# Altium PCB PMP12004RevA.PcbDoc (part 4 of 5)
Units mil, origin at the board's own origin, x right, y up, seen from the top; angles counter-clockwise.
Board outline 5500 x 4500 mil, 6 copper layers (Top Layer, GND, Signal Layer 1, Signal Layer 2, PWR Split, Bottom Layer), stack 0 mil thick; 355 components, 130 nets, 833 pads, 904 vias.
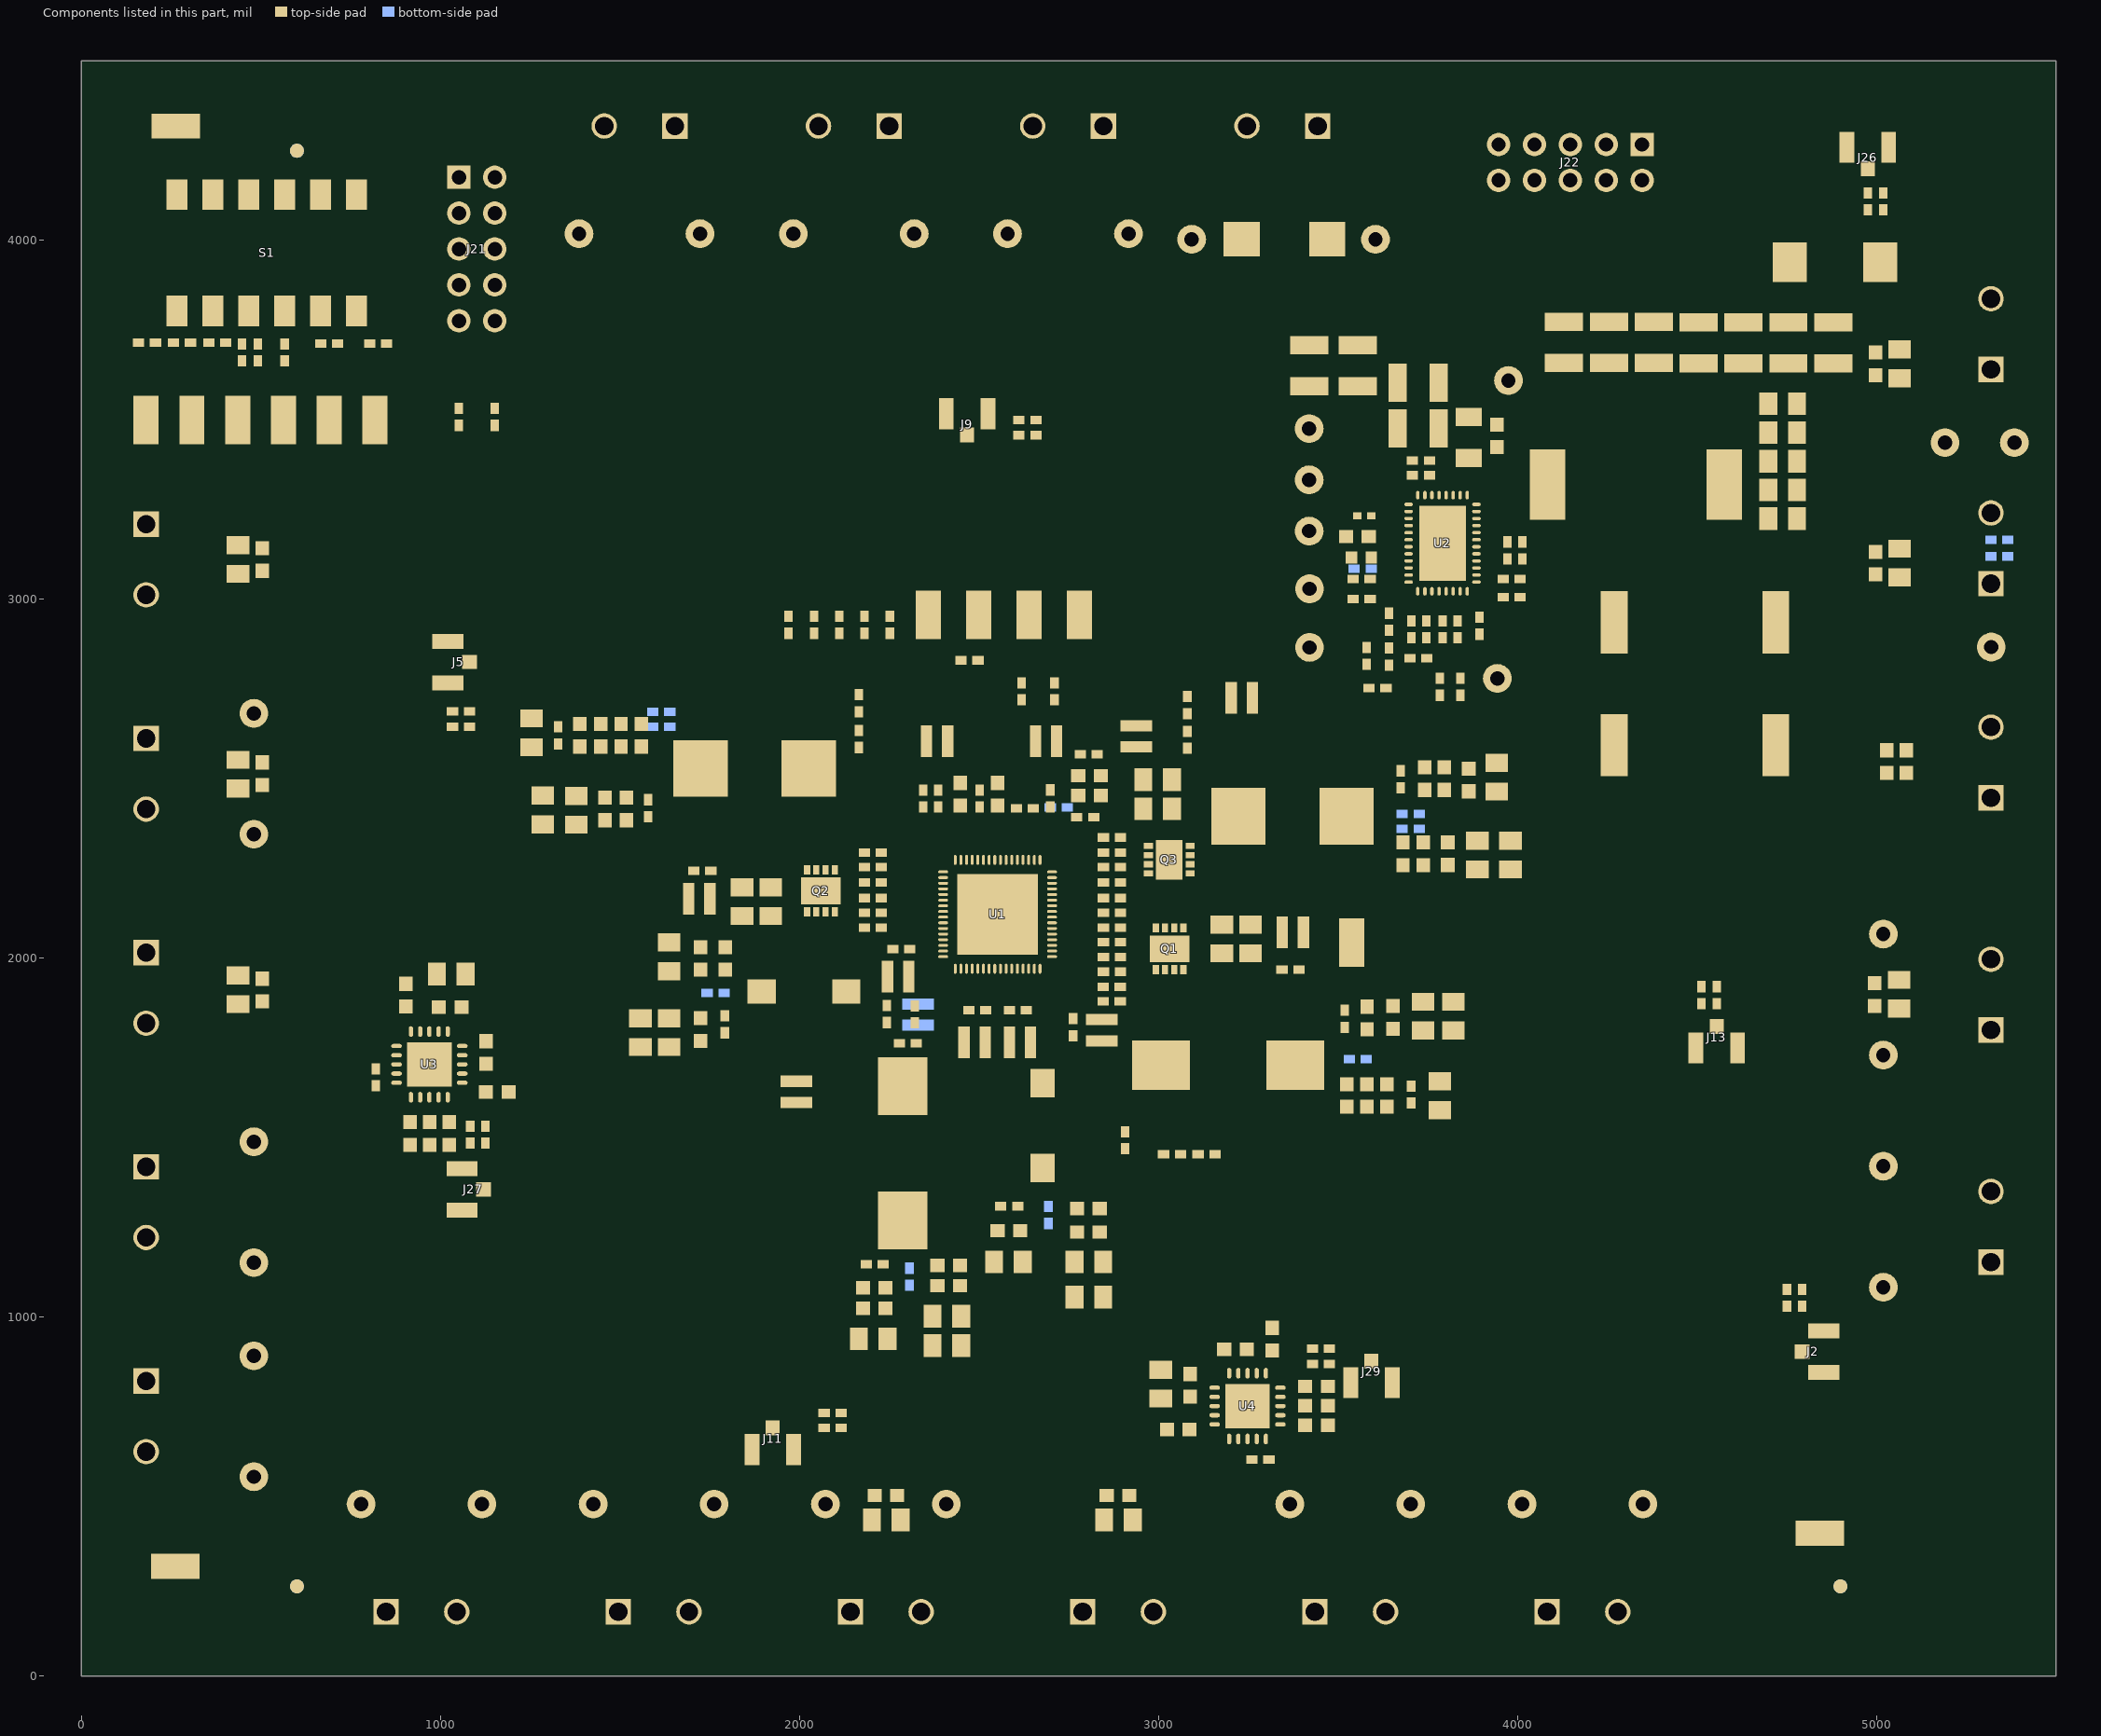
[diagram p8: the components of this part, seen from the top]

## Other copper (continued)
GND:
  pour cut-out: 1335.59,4019 1337.31,4032.05 1342.35,4044.22 1350.36,4054.66 1360.81,4062.67 1372.97,4067.71 1386.02,4069.43 1399.08,4067.71 1411.24,4062.67 1421.69,4054.66 1429.7,4044.22 1434.74,4032.05 1436.46,4019 1434.74,4005.95 1429.7,3993.78 1421.69,3983.34 1411.24,3975.33 1399.08,3970.29 1386.02,3968.57 1372.97,3970.29 1360.81,3975.33 1350.36,3983.34 1342.35,3993.78 1337.31,4005.95
  pour cut-out: 1672.44,4019 1674.16,4032.05 1679.2,4044.22 1687.21,4054.66 1697.66,4062.67 1709.82,4067.71 1722.87,4069.43 1735.93,4067.71 1748.09,4062.67 1758.54,4054.66 1766.55,4044.22 1771.59,4032.05 1773.31,4019 1771.59,4005.95 1766.55,3993.78 1758.54,3983.34 1748.09,3975.33 1735.93,3970.29 1722.87,3968.57 1709.82,3970.29 1697.66,3975.33 1687.21,3983.34 1679.2,3993.78 1674.16,4005.95
  pour cut-out: 1932.44,4019 1934.16,4032.05 1939.2,4044.22 1947.21,4054.66 1957.66,4062.67 1969.82,4067.71 1982.87,4069.43 1995.93,4067.71 2008.09,4062.67 2018.54,4054.66 2026.55,4044.22 2031.59,4032.05 2033.31,4019 2031.59,4005.95 2026.55,3993.78 2018.54,3983.34 2008.09,3975.33 1995.93,3970.29 1982.87,3968.57 1969.82,3970.29 1957.66,3975.33 1947.21,3983.34 1939.2,3993.78 1934.16,4005.95
  pour cut-out: 2269.29,4019 2271.01,4032.05 2276.05,4044.22 2284.06,4054.66 2294.51,4062.67 2306.67,4067.71 2319.72,4069.43 2332.78,4067.71 2344.94,4062.67 2355.39,4054.66 2363.4,4044.22 2368.44,4032.05 2370.16,4019 2368.44,4005.95 2363.4,3993.78 2355.39,3983.34 2344.94,3975.33 2332.78,3970.29 2319.72,3968.57 2306.67,3970.29 2294.51,3975.33 2284.06,3983.34 2276.05,3993.78 2271.01,4005.95
  pour cut-out: 2529.29,4019 2531.01,4032.05 2536.05,4044.22 2544.06,4054.66 2554.51,4062.67 2566.67,4067.71 2579.72,4069.43 2592.78,4067.71 2604.94,4062.67 2615.39,4054.66 2623.4,4044.22 2628.44,4032.05 2630.16,4019 2628.44,4005.95 2623.4,3993.78 2615.39,3983.34 2604.94,3975.33 2592.78,3970.29 2579.72,3968.57 2566.67,3970.29 2554.51,3975.33 2544.06,3983.34 2536.05,3993.78 2531.01,4005.95
  pour cut-out: 2866.14,4019 2867.86,4032.05 2872.9,4044.22 2880.91,4054.66 2891.36,4062.67 2903.52,4067.71 2916.57,4069.43 2929.63,4067.71 2941.79,4062.67 2952.24,4054.66 2960.25,4044.22 2965.29,4032.05 2967.01,4019 2965.29,4005.95 2960.25,3993.78 2952.24,3983.34 2941.79,3975.33 2929.63,3970.29 2916.57,3968.57 2903.52,3970.29 2891.36,3975.33 2880.91,3983.34 2872.9,3993.78 2867.86,4005.95
  pour cut-out: 4968.9,2067.19 4970.62,2080.25 4975.66,2092.41 4983.67,2102.85 4994.12,2110.87 5006.28,2115.91 5019.33,2117.63 5032.38,2115.91 5044.55,2110.87 5054.99,2102.85 5063.01,2092.41 5068.05,2080.25 5069.76,2067.19 5068.05,2054.14 5063.01,2041.98 5054.99,2031.53 5044.55,2023.52 5032.38,2018.48 5019.33,2016.76 5006.28,2018.48 4994.12,2023.52 4983.67,2031.53 4975.66,2041.98 4970.62,2054.14
  pour cut-out: 4968.9,1730.34 4970.62,1743.4 4975.66,1755.56 4983.67,1766 4994.12,1774.02 5006.28,1779.06 5019.33,1780.78 5032.38,1779.06 5044.55,1774.02 5054.99,1766 5063.01,1755.56 5068.05,1743.4 5069.76,1730.34 5068.05,1717.29 5063.01,1705.13 5054.99,1694.68 5044.55,1686.67 5032.38,1681.63 5019.33,1679.91 5006.28,1681.63 4994.12,1686.67 4983.67,1694.68 4975.66,1705.13 4970.62,1717.29
  pour cut-out: 4968.9,1420.34 4970.62,1433.4 4975.66,1445.56 4983.67,1456 4994.12,1464.02 5006.28,1469.06 5019.33,1470.78 5032.38,1469.06 5044.55,1464.02 5054.99,1456 5063.01,1445.56 5068.05,1433.4 5069.76,1420.34 5068.05,1407.29 5063.01,1395.13 5054.99,1384.68 5044.55,1376.67 5032.38,1371.63 5019.33,1369.91 5006.28,1371.63 4994.12,1376.67 4983.67,1384.68 4975.66,1395.13 4970.62,1407.29
  pour cut-out: 4968.9,1083.49 4970.62,1096.55 4975.66,1108.71 4983.67,1119.15 4994.12,1127.17 5006.28,1132.21 5019.33,1133.93 5032.38,1132.21 5044.55,1127.17 5054.99,1119.15 5063.01,1108.71 5068.05,1096.55 5069.76,1083.49 5068.05,1070.44 5063.01,1058.28 5054.99,1047.83 5044.55,1039.82 5032.38,1034.78 5019.33,1033.06 5006.28,1034.78 4994.12,1039.82 4983.67,1047.83 4975.66,1058.28 4970.62,1070.44
  pour cut-out: 4299.24,479 4300.96,492.05 4306,504.22 4314.01,514.66 4324.46,522.67 4336.62,527.71 4349.68,529.43 4362.73,527.71 4374.89,522.67 4385.34,514.66 4393.35,504.22 4398.39,492.05 4400.11,479 4398.39,465.95 4393.35,453.78 4385.34,443.34 4374.89,435.33 4362.73,430.29 4349.68,428.57 4336.62,430.29 4324.46,435.33 4314.01,443.34 4306,453.78 4300.96,465.95
  pour cut-out: 3962.39,479 3964.11,492.05 3969.15,504.22 3977.16,514.66 3987.61,522.67 3999.77,527.71 4012.83,529.43 4025.88,527.71 4038.04,522.67 4048.49,514.66 4056.5,504.22 4061.54,492.05 4063.26,479 4061.54,465.95 4056.5,453.78 4048.49,443.34 4038.04,435.33 4025.88,430.29 4012.83,428.57 3999.77,430.29 3987.61,435.33 3977.16,443.34 3969.15,453.78 3964.11,465.95
  pour cut-out: 3652.39,479 3654.11,492.05 3659.15,504.22 3667.16,514.66 3677.61,522.67 3689.77,527.71 3702.83,529.43 3715.88,527.71 3728.04,522.67 3738.49,514.66 3746.5,504.22 3751.54,492.05 3753.26,479 3751.54,465.95 3746.5,453.78 3738.49,443.34 3728.04,435.33 3715.88,430.29 3702.83,428.57 3689.77,430.29 3677.61,435.33 3667.16,443.34 3659.15,453.78 3654.11,465.95
  pour cut-out: 3315.54,479 3317.26,492.05 3322.3,504.22 3330.31,514.66 3340.76,522.67 3352.92,527.71 3365.98,529.43 3379.03,527.71 3391.19,522.67 3401.64,514.66 3409.65,504.22 3414.69,492.05 3416.41,479 3414.69,465.95 3409.65,453.78 3401.64,443.34 3391.19,435.33 3379.03,430.29 3365.98,428.57 3352.92,430.29 3340.76,435.33 3330.31,443.34 3322.3,453.78 3317.26,465.95
  pour cut-out: 2358.69,479 2360.41,492.05 2365.45,504.22 2373.46,514.66 2383.91,522.67 2396.07,527.71 2409.13,529.43 2422.18,527.71 2434.34,522.67 2444.79,514.66 2452.8,504.22 2457.84,492.05 2459.56,479 2457.84,465.95 2452.8,453.78 2444.79,443.34 2434.34,435.33 2422.18,430.29 2409.13,428.57 2396.07,430.29 2383.91,435.33 2373.46,443.34 2365.45,453.78 2360.41,465.95
  pour cut-out: 2021.84,479 2023.56,492.05 2028.6,504.22 2036.61,514.66 2047.06,522.67 2059.22,527.71 2072.28,529.43 2085.33,527.71 2097.49,522.67 2107.94,514.66 2115.95,504.22 2120.99,492.05 2122.71,479 2120.99,465.95 2115.95,453.78 2107.94,443.34 2097.49,435.33 2085.33,430.29 2072.28,428.57 2059.22,430.29 2047.06,435.33 2036.61,443.34 2028.6,453.78 2023.56,465.95
  pour cut-out: 1711.84,479 1713.56,492.05 1718.6,504.22 1726.61,514.66 1737.06,522.67 1749.22,527.71 1762.28,529.43 1775.33,527.71 1787.49,522.67 1797.94,514.66 1805.95,504.22 1810.99,492.05 1812.71,479 1810.99,465.95 1805.95,453.78 1797.94,443.34 1787.49,435.33 1775.33,430.29 1762.28,428.57 1749.22,430.29 1737.06,435.33 1726.61,443.34 1718.6,453.78 1713.56,465.95
  pour cut-out: 1374.99,479 1376.71,492.05 1381.75,504.22 1389.76,514.66 1400.21,522.67 1412.37,527.71 1425.43,529.43 1438.48,527.71 1450.64,522.67 1461.09,514.66 1469.1,504.22 1474.14,492.05 1475.86,479 1474.14,465.95 1469.1,453.78 1461.09,443.34 1450.64,435.33 1438.48,430.29 1425.43,428.57 1412.37,430.29 1400.21,435.33 1389.76,443.34 1381.75,453.78 1376.71,465.95
  pour cut-out: 1064.99,479 1066.71,492.05 1071.75,504.22 1079.76,514.66 1090.21,522.67 1102.37,527.71 1115.43,529.43 1128.48,527.71 1140.64,522.67 1151.09,514.66 1159.1,504.22 1164.14,492.05 1165.86,479 1164.14,465.95 1159.1,453.78 1151.09,443.34 1140.64,435.33 1128.48,430.29 1115.43,428.57 1102.37,430.29 1090.21,435.33 1079.76,443.34 1071.75,453.78 1066.71,465.95
  pour cut-out: 728.14,479 729.86,492.05 734.9,504.22 742.91,514.66 753.36,522.67 765.52,527.71 778.58,529.43 791.63,527.71 803.79,522.67 814.24,514.66 822.25,504.22 827.29,492.05 829.01,479 827.29,465.95 822.25,453.78 814.24,443.34 803.79,435.33 791.63,430.29 778.58,428.57 765.52,430.29 753.36,435.33 742.91,443.34 734.9,453.78 729.86,465.95
  pour cut-out: 429.57,555.17 431.29,568.23 436.33,580.39 444.34,590.84 454.78,598.85 466.95,603.89 480,605.61 493.05,603.89 505.22,598.85 515.66,590.84 523.67,580.39 528.71,568.23 530.43,555.17 528.71,542.12 523.67,529.96 515.66,519.51 505.22,511.5 493.05,506.46 480,504.74 466.95,506.46 454.78,511.5 444.34,519.51 436.33,529.96 431.29,542.12
  pour cut-out: 429.57,892.02 431.29,905.08 436.33,917.24 444.34,927.69 454.78,935.7 466.95,940.74 480,942.46 493.05,940.74 505.22,935.7 515.66,927.69 523.67,917.24 528.71,905.08 530.43,892.02 528.71,878.97 523.67,866.81 515.66,856.36 505.22,848.35 493.05,843.31 480,841.59 466.95,843.31 454.78,848.35 444.34,856.36 436.33,866.81 431.29,878.97
  pour cut-out: 429.57,1488.87 431.29,1501.93 436.33,1514.09 444.34,1524.54 454.78,1532.55 466.95,1537.59 480,1539.31 493.05,1537.59 505.22,1532.55 515.66,1524.54 523.67,1514.09 528.71,1501.93 530.43,1488.87 528.71,1475.82 523.67,1463.66 515.66,1453.21 505.22,1445.2 493.05,1440.16 480,1438.44 466.95,1440.16 454.78,1445.2 444.34,1453.21 436.33,1463.66 431.29,1475.82
  pour cut-out: 429.57,2345.72 431.29,2358.78 436.33,2370.94 444.34,2381.39 454.78,2389.4 466.95,2394.44 480,2396.16 493.05,2394.44 505.22,2389.4 515.66,2381.39 523.67,2370.94 528.71,2358.78 530.43,2345.72 528.71,2332.67 523.67,2320.51 515.66,2310.06 505.22,2302.05 493.05,2297.01 480,2295.29 466.95,2297.01 454.78,2302.05 444.34,2310.06 436.33,2320.51 431.29,2332.67
  pour cut-out: 429.57,2682.57 431.29,2695.63 436.33,2707.79 444.34,2718.24 454.78,2726.25 466.95,2731.29 480,2733.01 493.05,2731.29 505.22,2726.25 515.66,2718.24 523.67,2707.79 528.71,2695.63 530.43,2682.57 528.71,2669.52 523.67,2657.36 515.66,2646.91 505.22,2638.9 493.05,2633.86 480,2632.14 466.95,2633.86 454.78,2638.9 444.34,2646.91 436.33,2657.36 431.29,2669.52
  pour cut-out: 429.57,1152.02 431.29,1165.08 436.33,1177.24 444.34,1187.69 454.78,1195.7 466.95,1200.74 480,1202.46 493.05,1200.74 505.22,1195.7 515.66,1187.69 523.67,1177.24 528.71,1165.08 530.43,1152.02 528.71,1138.97 523.67,1126.81 515.66,1116.36 505.22,1108.35 493.05,1103.31 480,1101.59 466.95,1103.31 454.78,1108.35 444.34,1116.36 436.33,1126.81 431.29,1138.97
  pour cut-out: 5269.66,2867.18 5271.38,2880.23 5276.42,2892.39 5284.43,2902.84 5294.87,2910.85 5307.04,2915.89 5320.09,2917.61 5333.14,2915.89 5345.31,2910.85 5355.75,2902.84 5363.76,2892.39 5368.8,2880.23 5370.52,2867.18 5368.8,2854.12 5363.76,2841.96 5355.75,2831.52 5345.31,2823.5 5333.14,2818.46 5320.09,2816.74 5307.04,2818.46 5294.87,2823.5 5284.43,2831.52 5276.42,2841.96 5271.38,2854.12
  pour cut-out: 2310.49,2160.97 cw(c2310.49,2175.97) 2295.49,2175.97 cw(c2310.49,2175.97) 2310.49,2190.97 cw(c2310.49,2175.97) 2325.49,2175.97 cw(c2310.49,2175.97)
  pour cut-out: 2780.69,2112.34 cw(c2780.69,2127.34) 2765.69,2127.34 cw(c2780.69,2127.34) 2780.69,2142.34 cw(c2780.69,2127.34) 2795.69,2127.34 cw(c2780.69,2127.34)
  pour cut-out: 2785.08,2036.6 cw(c2785.08,2051.6) 2770.08,2051.6 cw(c2785.08,2051.6) 2785.08,2066.6 cw(c2785.08,2051.6) 2800.08,2051.6 cw(c2785.08,2051.6)
  pour cut-out: 3037.13,2179.63 cw(c3037.13,2194.63) 3022.13,2194.63 cw(c3037.13,2194.63) 3037.13,2209.63 cw(c3037.13,2194.63) 3052.13,2194.63 cw(c3037.13,2194.63)
  pour cut-out: 2952.65,2003.85 cw(c2952.65,2018.85) 2937.65,2018.85 cw(c2952.65,2018.85) 2952.65,2033.85 cw(c2952.65,2018.85) 2967.65,2018.85 cw(c2952.65,2018.85)
  pour cut-out: 2138.36,2180.07 cw(c2138.36,2195.07) 2123.36,2195.07 cw(c2138.36,2195.07) 2138.36,2210.07 cw(c2138.36,2195.07) 2153.36,2195.07 cw(c2138.36,2195.07)
  text "2" at 4712.44,637.86 h100
  text ".Layer_Name" at 577,-858.49 h60
Signal Layer 1:
  pour cut-out: 1335.59,4019 1337.31,4032.05 1342.35,4044.22 1350.36,4054.66 1360.81,4062.67 1372.97,4067.71 1386.02,4069.43 1399.08,4067.71 1411.24,4062.67 1421.69,4054.66 1429.7,4044.22 1434.74,4032.05 1436.46,4019 1434.74,4005.95 1429.7,3993.78 1421.69,3983.34 1411.24,3975.33 1399.08,3970.29 1386.02,3968.57 1372.97,3970.29 1360.81,3975.33 1350.36,3983.34 1342.35,3993.78 1337.31,4005.95
  pour cut-out: 1672.44,4019 1674.16,4032.05 1679.2,4044.22 1687.21,4054.66 1697.66,4062.67 1709.82,4067.71 1722.87,4069.43 1735.93,4067.71 1748.09,4062.67 1758.54,4054.66 1766.55,4044.22 1771.59,4032.05 1773.31,4019 1771.59,4005.95 1766.55,3993.78 1758.54,3983.34 1748.09,3975.33 1735.93,3970.29 1722.87,3968.57 1709.82,3970.29 1697.66,3975.33 1687.21,3983.34 1679.2,3993.78 1674.16,4005.95
  pour cut-out: 1932.44,4019 1934.16,4032.05 1939.2,4044.22 1947.21,4054.66 1957.66,4062.67 1969.82,4067.71 1982.87,4069.43 1995.93,4067.71 2008.09,4062.67 2018.54,4054.66 2026.55,4044.22 2031.59,4032.05 2033.31,4019 2031.59,4005.95 2026.55,3993.78 2018.54,3983.34 2008.09,3975.33 1995.93,3970.29 1982.87,3968.57 1969.82,3970.29 1957.66,3975.33 1947.21,3983.34 1939.2,3993.78 1934.16,4005.95
  pour cut-out: 2269.29,4019 2271.01,4032.05 2276.05,4044.22 2284.06,4054.66 2294.51,4062.67 2306.67,4067.71 2319.72,4069.43 2332.78,4067.71 2344.94,4062.67 2355.39,4054.66 2363.4,4044.22 2368.44,4032.05 2370.16,4019 2368.44,4005.95 2363.4,3993.78 2355.39,3983.34 2344.94,3975.33 2332.78,3970.29 2319.72,3968.57 2306.67,3970.29 2294.51,3975.33 2284.06,3983.34 2276.05,3993.78 2271.01,4005.95
  pour cut-out: 2529.29,4019 2531.01,4032.05 2536.05,4044.22 2544.06,4054.66 2554.51,4062.67 2566.67,4067.71 2579.72,4069.43 2592.78,4067.71 2604.94,4062.67 2615.39,4054.66 2623.4,4044.22 2628.44,4032.05 2630.16,4019 2628.44,4005.95 2623.4,3993.78 2615.39,3983.34 2604.94,3975.33 2592.78,3970.29 2579.72,3968.57 2566.67,3970.29 2554.51,3975.33 2544.06,3983.34 2536.05,3993.78 2531.01,4005.95
  pour cut-out: 2866.14,4019 2867.86,4032.05 2872.9,4044.22 2880.91,4054.66 2891.36,4062.67 2903.52,4067.71 2916.57,4069.43 2929.63,4067.71 2941.79,4062.67 2952.24,4054.66 2960.25,4044.22 2965.29,4032.05 2967.01,4019 2965.29,4005.95 2960.25,3993.78 2952.24,3983.34 2941.79,3975.33 2929.63,3970.29 2916.57,3968.57 2903.52,3970.29 2891.36,3975.33 2880.91,3983.34 2872.9,3993.78 2867.86,4005.95
  pour cut-out: 4968.9,2067.19 4970.62,2080.25 4975.66,2092.41 4983.67,2102.85 4994.12,2110.87 5006.28,2115.91 5019.33,2117.63 5032.38,2115.91 5044.55,2110.87 5054.99,2102.85 5063.01,2092.41 5068.05,2080.25 5069.76,2067.19 5068.05,2054.14 5063.01,2041.98 5054.99,2031.53 5044.55,2023.52 5032.38,2018.48 5019.33,2016.76 5006.28,2018.48 4994.12,2023.52 4983.67,2031.53 4975.66,2041.98 4970.62,2054.14
  pour cut-out: 4968.9,1730.34 4970.62,1743.4 4975.66,1755.56 4983.67,1766 4994.12,1774.02 5006.28,1779.06 5019.33,1780.78 5032.38,1779.06 5044.55,1774.02 5054.99,1766 5063.01,1755.56 5068.05,1743.4 5069.76,1730.34 5068.05,1717.29 5063.01,1705.13 5054.99,1694.68 5044.55,1686.67 5032.38,1681.63 5019.33,1679.91 5006.28,1681.63 4994.12,1686.67 4983.67,1694.68 4975.66,1705.13 4970.62,1717.29
  pour cut-out: 4968.9,1420.34 4970.62,1433.4 4975.66,1445.56 4983.67,1456 4994.12,1464.02 5006.28,1469.06 5019.33,1470.78 5032.38,1469.06 5044.55,1464.02 5054.99,1456 5063.01,1445.56 5068.05,1433.4 5069.76,1420.34 5068.05,1407.29 5063.01,1395.13 5054.99,1384.68 5044.55,1376.67 5032.38,1371.63 5019.33,1369.91 5006.28,1371.63 4994.12,1376.67 4983.67,1384.68 4975.66,1395.13 4970.62,1407.29
  pour cut-out: 4968.9,1083.49 4970.62,1096.55 4975.66,1108.71 4983.67,1119.15 4994.12,1127.17 5006.28,1132.21 5019.33,1133.93 5032.38,1132.21 5044.55,1127.17 5054.99,1119.15 5063.01,1108.71 5068.05,1096.55 5069.76,1083.49 5068.05,1070.44 5063.01,1058.28 5054.99,1047.83 5044.55,1039.82 5032.38,1034.78 5019.33,1033.06 5006.28,1034.78 4994.12,1039.82 4983.67,1047.83 4975.66,1058.28 4970.62,1070.44
  pour cut-out: 4299.24,479 4300.96,492.05 4306,504.22 4314.01,514.66 4324.46,522.67 4336.62,527.71 4349.68,529.43 4362.73,527.71 4374.89,522.67 4385.34,514.66 4393.35,504.22 4398.39,492.05 4400.11,479 4398.39,465.95 4393.35,453.78 4385.34,443.34 4374.89,435.33 4362.73,430.29 4349.68,428.57 4336.62,430.29 4324.46,435.33 4314.01,443.34 4306,453.78 4300.96,465.95
  pour cut-out: 3962.39,479 3964.11,492.05 3969.15,504.22 3977.16,514.66 3987.61,522.67 3999.77,527.71 4012.83,529.43 4025.88,527.71 4038.04,522.67 4048.49,514.66 4056.5,504.22 4061.54,492.05 4063.26,479 4061.54,465.95 4056.5,453.78 4048.49,443.34 4038.04,435.33 4025.88,430.29 4012.83,428.57 3999.77,430.29 3987.61,435.33 3977.16,443.34 3969.15,453.78 3964.11,465.95
  pour cut-out: 3652.39,479 3654.11,492.05 3659.15,504.22 3667.16,514.66 3677.61,522.67 3689.77,527.71 3702.83,529.43 3715.88,527.71 3728.04,522.67 3738.49,514.66 3746.5,504.22 3751.54,492.05 3753.26,479 3751.54,465.95 3746.5,453.78 3738.49,443.34 3728.04,435.33 3715.88,430.29 3702.83,428.57 3689.77,430.29 3677.61,435.33 3667.16,443.34 3659.15,453.78 3654.11,465.95
  pour cut-out: 3315.54,479 3317.26,492.05 3322.3,504.22 3330.31,514.66 3340.76,522.67 3352.92,527.71 3365.98,529.43 3379.03,527.71 3391.19,522.67 3401.64,514.66 3409.65,504.22 3414.69,492.05 3416.41,479 3414.69,465.95 3409.65,453.78 3401.64,443.34 3391.19,435.33 3379.03,430.29 3365.98,428.57 3352.92,430.29 3340.76,435.33 3330.31,443.34 3322.3,453.78 3317.26,465.95
  pour cut-out: 2358.69,479 2360.41,492.05 2365.45,504.22 2373.46,514.66 2383.91,522.67 2396.07,527.71 2409.13,529.43 2422.18,527.71 2434.34,522.67 2444.79,514.66 2452.8,504.22 2457.84,492.05 2459.56,479 2457.84,465.95 2452.8,453.78 2444.79,443.34 2434.34,435.33 2422.18,430.29 2409.13,428.57 2396.07,430.29 2383.91,435.33 2373.46,443.34 2365.45,453.78 2360.41,465.95
  pour cut-out: 2021.84,479 2023.56,492.05 2028.6,504.22 2036.61,514.66 2047.06,522.67 2059.22,527.71 2072.28,529.43 2085.33,527.71 2097.49,522.67 2107.94,514.66 2115.95,504.22 2120.99,492.05 2122.71,479 2120.99,465.95 2115.95,453.78 2107.94,443.34 2097.49,435.33 2085.33,430.29 2072.28,428.57 2059.22,430.29 2047.06,435.33 2036.61,443.34 2028.6,453.78 2023.56,465.95
  pour cut-out: 1711.84,479 1713.56,492.05 1718.6,504.22 1726.61,514.66 1737.06,522.67 1749.22,527.71 1762.28,529.43 1775.33,527.71 1787.49,522.67 1797.94,514.66 1805.95,504.22 1810.99,492.05 1812.71,479 1810.99,465.95 1805.95,453.78 1797.94,443.34 1787.49,435.33 1775.33,430.29 1762.28,428.57 1749.22,430.29 1737.06,435.33 1726.61,443.34 1718.6,453.78 1713.56,465.95
  pour cut-out: 1374.99,479 1376.71,492.05 1381.75,504.22 1389.76,514.66 1400.21,522.67 1412.37,527.71 1425.43,529.43 1438.48,527.71 1450.64,522.67 1461.09,514.66 1469.1,504.22 1474.14,492.05 1475.86,479 1474.14,465.95 1469.1,453.78 1461.09,443.34 1450.64,435.33 1438.48,430.29 1425.43,428.57 1412.37,430.29 1400.21,435.33 1389.76,443.34 1381.75,453.78 1376.71,465.95
  pour cut-out: 1064.99,479 1066.71,492.05 1071.75,504.22 1079.76,514.66 1090.21,522.67 1102.37,527.71 1115.43,529.43 1128.48,527.71 1140.64,522.67 1151.09,514.66 1159.1,504.22 1164.14,492.05 1165.86,479 1164.14,465.95 1159.1,453.78 1151.09,443.34 1140.64,435.33 1128.48,430.29 1115.43,428.57 1102.37,430.29 1090.21,435.33 1079.76,443.34 1071.75,453.78 1066.71,465.95
  pour cut-out: 728.14,479 729.86,492.05 734.9,504.22 742.91,514.66 753.36,522.67 765.52,527.71 778.58,529.43 791.63,527.71 803.79,522.67 814.24,514.66 822.25,504.22 827.29,492.05 829.01,479 827.29,465.95 822.25,453.78 814.24,443.34 803.79,435.33 791.63,430.29 778.58,428.57 765.52,430.29 753.36,435.33 742.91,443.34 734.9,453.78 729.86,465.95
  pour cut-out: 429.57,555.17 431.29,568.23 436.33,580.39 444.34,590.84 454.78,598.85 466.95,603.89 480,605.61 493.05,603.89 505.22,598.85 515.66,590.84 523.67,580.39 528.71,568.23 530.43,555.17 528.71,542.12 523.67,529.96 515.66,519.51 505.22,511.5 493.05,506.46 480,504.74 466.95,506.46 454.78,511.5 444.34,519.51 436.33,529.96 431.29,542.12
  pour cut-out: 429.57,892.02 431.29,905.08 436.33,917.24 444.34,927.69 454.78,935.7 466.95,940.74 480,942.46 493.05,940.74 505.22,935.7 515.66,927.69 523.67,917.24 528.71,905.08 530.43,892.02 528.71,878.97 523.67,866.81 515.66,856.36 505.22,848.35 493.05,843.31 480,841.59 466.95,843.31 454.78,848.35 444.34,856.36 436.33,866.81 431.29,878.97
  pour cut-out: 429.57,1488.87 431.29,1501.93 436.33,1514.09 444.34,1524.54 454.78,1532.55 466.95,1537.59 480,1539.31 493.05,1537.59 505.22,1532.55 515.66,1524.54 523.67,1514.09 528.71,1501.93 530.43,1488.87 528.71,1475.82 523.67,1463.66 515.66,1453.21 505.22,1445.2 493.05,1440.16 480,1438.44 466.95,1440.16 454.78,1445.2 444.34,1453.21 436.33,1463.66 431.29,1475.82
  pour cut-out: 429.57,2345.72 431.29,2358.78 436.33,2370.94 444.34,2381.39 454.78,2389.4 466.95,2394.44 480,2396.16 493.05,2394.44 505.22,2389.4 515.66,2381.39 523.67,2370.94 528.71,2358.78 530.43,2345.72 528.71,2332.67 523.67,2320.51 515.66,2310.06 505.22,2302.05 493.05,2297.01 480,2295.29 466.95,2297.01 454.78,2302.05 444.34,2310.06 436.33,2320.51 431.29,2332.67
  pour cut-out: 429.57,2682.57 431.29,2695.63 436.33,2707.79 444.34,2718.24 454.78,2726.25 466.95,2731.29 480,2733.01 493.05,2731.29 505.22,2726.25 515.66,2718.24 523.67,2707.79 528.71,2695.63 530.43,2682.57 528.71,2669.52 523.67,2657.36 515.66,2646.91 505.22,2638.9 493.05,2633.86 480,2632.14 466.95,2633.86 454.78,2638.9 444.34,2646.91 436.33,2657.36 431.29,2669.52
  pour cut-out: 429.57,1152.02 431.29,1165.08 436.33,1177.24 444.34,1187.69 454.78,1195.7 466.95,1200.74 480,1202.46 493.05,1200.74 505.22,1195.7 515.66,1187.69 523.67,1177.24 528.71,1165.08 530.43,1152.02 528.71,1138.97 523.67,1126.81 515.66,1116.36 505.22,1108.35 493.05,1103.31 480,1101.59 466.95,1103.31 454.78,1108.35 444.34,1116.36 436.33,1126.81 431.29,1138.97
  pour cut-out: 429.51,891.75 429.51,763.74 492.87,700.38 503.48,711 905.29,711 2008.94,1814.65 2161.01,1814.65 2188.63,1842.27 2218.19,1871.84 2237.42,1871.84 2282.86,1917.27 2282.86,2030.16 2206.03,2106.99 2134.55,2106.99 2124.57,2097.02 2124.57,2078.52 2135.95,2067.14 2196.46,2067.14 2247.69,2015.9 2247.69,1938.33 2219.96,1910.59 2200.74,1910.59 2152.69,1862.55 2144.04,1853.9 1992.82,1853.9 893.21,754.29 522.48,754.29 504.65,772.12 504.65,814.12 530.43,839.91 530.43,898.34
  pour cut-out: 778.58,428.57 925.37,428.57 960.81,464.01 960.81,497.6 956.35,502.05 956.35,565.48 2075.81,1684.94 2276.16,1684.94 2338.68,1747.45 2338.68,1856.45 2308.5,1886.63 2251.76,1886.63 2236.96,1871.84 2219.31,1871.84 2188.47,1840.99 2188.47,1760.69 2153.89,1726.11 2057.97,1726.11 915.72,583.86 915.72,512.57 908.44,505.29 838.15,505.29 814,529.43 778.58,529.43
  pour cut-out: 2072.28,428.57 2110.72,428.57 2132.97,450.81 2225.08,450.81 2258.86,484.59 2258.86,1174.57 2233.4,1200.02 2176.04,1200.02 2160.95,1184.93 2160.95,1164.66 2172.08,1153.53 2210.41,1153.53 2216.84,1147.11 2216.84,522.21 2198.04,503.41 2139.62,503.41 2113.6,529.43 2072.28,529.43
  pour cut-out: 2876.36,1463.34 2876.36,1433.8 2889.29,1420.87 2926.56,1420.87 2940.29,1434.61 2940.29,1455.01 2947.33,1462.06 3068.33,1462.06 3362.12,1168.26 3735.78,1168.26 4176.31,727.74 4176.31,517.32 4157.93,498.95 4087.75,498.95 4057.26,529.43 4012.83,529.43 4012.83,428.57 4058.23,428.57 4081.35,451.69 4182.81,451.69 4220.88,489.75 4220.88,743.91 3755.14,1209.64 3378.39,1209.64 3088.85,1499.18 2912.48,1499.18
  pour cut-out: 3486.24,1619.61 3486.24,1504.5 3499.06,1491.68 3519.68,1491.68 3533.43,1505.43 3533.43,1583.49 3551.52,1601.58 4254.78,1601.58 4633.54,1222.82 4984.89,1222.82 5001.13,1206.58 5001.13,1159.99 4968.9,1127.76 4968.9,1083.49 5069.76,1083.49 5069.76,1131.98 5044.63,1157.12 5044.63,1232.63 5009.15,1268.11 4653.92,1268.11 4280.37,1641.66 3508.3,1641.66
  pour cut-out: 3617.65,2372 3617.65,2348.38 3629.77,2336.26 3651.04,2336.26 3661.36,2346.58 4129.18,2346.58 4592.44,1883.32 4981.73,1883.32 4999.9,1865.15 4999.9,1805.66 4968.9,1774.66 4968.9,1730.34 5069.76,1730.34 5069.76,1772.15 5042.53,1799.38 5042.53,1894.89 5006.52,1930.9 4608.31,1930.9 4145.86,2393.35 3639.03,2393.35
  pour cut-out: 429.57,2682.57 429.57,2547.78 468.31,2509.04 839.99,2509.04 948.29,2617.33 1587.68,2617.33 1613.13,2642.78 1613.13,2728.91 1595.73,2746.3 1575.77,2746.3 1561.23,2731.76 1561.23,2669.04 1551.23,2659.04 928.12,2659.04 822.09,2553.01 520.28,2553.01 505.34,2567.95 505.34,2607.51 530.43,2632.61 530.43,2682.57
  pour cut-out: 1581.07,4010.37 1620.47,4049.76 1654.64,4049.77 1674.3,4069.43 1723.18,4069.43 1723.18,3968.56 1690.17,3968.56 1669.08,3989.65 1651.7,3989.65 1630.94,3968.89 1630.94,3870.35 2628.01,2873.28 2628.01,2823.1 2666.78,2784.34 2666.78,2739.52 2650.37,2723.11 2630.02,2723.11 2587.74,2765.39 2587.74,2849.74 1581.07,3856.41
  pour cut-out: 2173.69,4014.18 2208.32,4048.81 2249.04,4048.81 2269.67,4069.43 2320.01,4069.43 2320.01,3968.71 2295.4,3968.71 2271.72,3992.39 2242.97,3992.39 2225.99,3975.41 2225.99,3597.35 2712.29,3111.05 2712.29,2836.05 2741.26,2807.08 2741.26,2774.88 2727.31,2760.93 2695.37,2760.92 2666.71,2789.59 2666.71,3086.31 2173.69,3579.33
  pour cut-out: 2762.07,2573.12 2762.07,4013.62 2793.03,4044.59 2857.21,4044.59 2881.64,4069.02 2917.02,4069.02 2917.02,3968.57 2890.97,3968.57 2865.71,3993.83 2828.06,3993.83 2811.56,3977.33 2811.56,2651.62 2857.06,2606.12 2857.06,2587.84 2836.95,2567.73 2836.95,2555.09 2854.06,2537.97 2854.06,2453.57 2875.42,2432.22 2882.75,2432.22 2893.72,2421.24 2893.72,2404.45 2881.52,2392.25 2865.61,2392.25 2817.05,2440.81 2817.05,2518.14
  pour cut-out: 157.86,3377.68 195.72,3339.81 195.72,3327.57 210.15,3313.15 210.15,3280.33 256.61,3233.88 256.61,2821.59 194.98,2759.96 194.98,2721.04 206.41,2709.61 206.41,2684.15 239.62,2650.94 239.62,2496.41 184.59,2441.37 173.88,2441.37 155.28,2459.98
  pour cut-out: 2553.46,1324.03 2541.88,1335.61 2541.88,1360.45 2554.04,1372.61 2606.75,1372.7 2637.07,1342.38 2637.07,975.98 2922.58,690.47 3124.1,690.47 3141.76,708.14 3186.76,708.14 3221.13,673.76 3425.05,673.76 3562.54,536.28 3562.54,501.81 3570.21,494.14 3570.21,478.89 3546.28,454.96 3440.46,454.96 3413.44,427.94 3366.61,427.94 3365.98,428.57 3365.98,529.43 3409.42,529.43 3441.34,497.51 3510.81,497.51 3519.22,505.92 3519.22,524.24 3407.49,635.97 3205.41,635.97 3176.14,665.24 3153.21,665.24 3139.69,651.71 2900.55,651.71 2593.96,958.3 2593.96,1317.13 2587.07,1324.03
  pour cut-out: 1835.18,2029.42 1844.78,2039.02 1869.41,2039.02 1880.29,2028.14 1880.29,1984.65 1844.39,1948.75 1624.51,1948.75 1246.62,1570.85 1246.62,1437.49 1119.12,1310 487.43,1310 455.17,1342.26 455.17,1408.9 429.57,1434.5 429.57,1488.33 529.89,1488.33 530.43,1488.87 530.43,1432.51 506.78,1408.86 506.78,1373.97 525.35,1355.41 1095.86,1355.41 1201.73,1461.28 1201.73,1586.83 1602.5,1987.6 1817.99,1987.6 1835.18,2004.79
  pour cut-out: 5294,2895.13 5294,3048.97 5308.6,3063.57 5332.94,3063.57 5344.82,3051.69 5344.82,2874.88 5329.05,2859.11 5316.37,2859.11 5293.99,2881.49
  pour cut-out: 5269.66,2867.18 5271.38,2880.23 5276.42,2892.39 5284.43,2902.84 5294.87,2910.85 5307.04,2915.89 5320.09,2917.61 5333.14,2915.89 5345.31,2910.85 5355.75,2902.84 5363.76,2892.39 5368.8,2880.23 5370.52,2867.18 5368.8,2854.12 5363.76,2841.96 5355.75,2831.52 5345.31,2823.5 5333.14,2818.46 5320.09,2816.74 5307.04,2818.46 5294.87,2823.5 5284.43,2831.52 5276.42,2841.96 5271.38,2854.12
  pour cut-out: 5268.9,2644.04 5270.62,2657.1 5275.66,2669.26 5283.67,2679.71 5294.12,2687.72 5306.28,2692.76 5319.33,2694.48 5332.38,2692.76 5344.55,2687.72 5354.99,2679.71 5363.01,2669.26 5368.05,2657.1 5369.76,2644.04 5368.05,2630.99 5363.01,2618.83 5354.99,2608.38 5344.55,2600.37 5332.38,2595.33 5319.33,2593.61 5306.28,2595.33 5294.12,2600.37 5283.67,2608.38 5275.66,2618.83 5270.62,2630.99
  pour cut-out: 2310.49,2160.97 cw(c2310.49,2175.97) 2295.49,2175.97 cw(c2310.49,2175.97) 2310.49,2190.97 cw(c2310.49,2175.97) 2325.49,2175.97 cw(c2310.49,2175.97)
  pour cut-out: 2780.69,2112.34 cw(c2780.69,2127.34) 2765.69,2127.34 cw(c2780.69,2127.34) 2780.69,2142.34 cw(c2780.69,2127.34) 2795.69,2127.34 cw(c2780.69,2127.34)
  pour cut-out: 2785.08,2036.6 cw(c2785.08,2051.6) 2770.08,2051.6 cw(c2785.08,2051.6) 2785.08,2066.6 cw(c2785.08,2051.6) 2800.08,2051.6 cw(c2785.08,2051.6)
  pour cut-out: 3037.13,2179.63 cw(c3037.13,2194.63) 3022.13,2194.63 cw(c3037.13,2194.63) 3037.13,2209.63 cw(c3037.13,2194.63) 3052.13,2194.63 cw(c3037.13,2194.63)
  pour cut-out: 2952.65,2003.85 cw(c2952.65,2018.85) 2937.65,2018.85 cw(c2952.65,2018.85) 2952.65,2033.85 cw(c2952.65,2018.85) 2967.65,2018.85 cw(c2952.65,2018.85)
  pour cut-out: 2138.36,2180.07 cw(c2138.36,2195.07) 2123.36,2195.07 cw(c2138.36,2195.07) 2138.36,2210.07 cw(c2138.36,2195.07) 2153.36,2195.07 cw(c2138.36,2195.07)
  text "3" at 4862.44,637.86 h100
  text ".Layer_Name" at 577,-858.49 h60
Signal Layer 2:
  pour cut-out: 1193.47,1743.88 1216.83,1720.51 1212.32,1716 1199.07,1716 1187.53,1727.55 1187.53,1736.65
  pour cut-out: 4652.21,2551.28 4347.27,2551.28 4347.21,2551.21 4347.21,2559.78 4347.23,2559.8 4652.17,2559.8 4652.24,2559.72
  pour cut-out: 1464.91,2093.12 1564.95,1993.08 1684.17,1993.08 1689.96,1998.87 1689.96,2099.82 1687.42,2102.36 1668.24,2102.36 1661.31,2095.43 1466.76,2095.43
  pour cut-out: 1335.59,4019 1337.31,4032.05 1342.35,4044.22 1350.36,4054.66 1360.81,4062.67 1372.97,4067.71 1386.02,4069.43 1399.08,4067.71 1411.24,4062.67 1421.69,4054.66 1429.7,4044.22 1434.74,4032.05 1436.46,4019 1434.74,4005.95 1429.7,3993.78 1421.69,3983.34 1411.24,3975.33 1399.08,3970.29 1386.02,3968.57 1372.97,3970.29 1360.81,3975.33 1350.36,3983.34 1342.35,3993.78 1337.31,4005.95
  pour cut-out: 1672.44,4019 1674.16,4032.05 1679.2,4044.22 1687.21,4054.66 1697.66,4062.67 1709.82,4067.71 1722.87,4069.43 1735.93,4067.71 1748.09,4062.67 1758.54,4054.66 1766.55,4044.22 1771.59,4032.05 1773.31,4019 1771.59,4005.95 1766.55,3993.78 1758.54,3983.34 1748.09,3975.33 1735.93,3970.29 1722.87,3968.57 1709.82,3970.29 1697.66,3975.33 1687.21,3983.34 1679.2,3993.78 1674.16,4005.95
  pour cut-out: 1932.44,4019 1934.16,4032.05 1939.2,4044.22 1947.21,4054.66 1957.66,4062.67 1969.82,4067.71 1982.87,4069.43 1995.93,4067.71 2008.09,4062.67 2018.54,4054.66 2026.55,4044.22 2031.59,4032.05 2033.31,4019 2031.59,4005.95 2026.55,3993.78 2018.54,3983.34 2008.09,3975.33 1995.93,3970.29 1982.87,3968.57 1969.82,3970.29 1957.66,3975.33 1947.21,3983.34 1939.2,3993.78 1934.16,4005.95
  pour cut-out: 2269.29,4019 2271.01,4032.05 2276.05,4044.22 2284.06,4054.66 2294.51,4062.67 2306.67,4067.71 2319.72,4069.43 2332.78,4067.71 2344.94,4062.67 2355.39,4054.66 2363.4,4044.22 2368.44,4032.05 2370.16,4019 2368.44,4005.95 2363.4,3993.78 2355.39,3983.34 2344.94,3975.33 2332.78,3970.29 2319.72,3968.57 2306.67,3970.29 2294.51,3975.33 2284.06,3983.34 2276.05,3993.78 2271.01,4005.95
  pour cut-out: 2529.29,4019 2531.01,4032.05 2536.05,4044.22 2544.06,4054.66 2554.51,4062.67 2566.67,4067.71 2579.72,4069.43 2592.78,4067.71 2604.94,4062.67 2615.39,4054.66 2623.4,4044.22 2628.44,4032.05 2630.16,4019 2628.44,4005.95 2623.4,3993.78 2615.39,3983.34 2604.94,3975.33 2592.78,3970.29 2579.72,3968.57 2566.67,3970.29 2554.51,3975.33 2544.06,3983.34 2536.05,3993.78 2531.01,4005.95
  pour cut-out: 2866.14,4019 2867.86,4032.05 2872.9,4044.22 2880.91,4054.66 2891.36,4062.67 2903.52,4067.71 2916.57,4069.43 2929.63,4067.71 2941.79,4062.67 2952.24,4054.66 2960.25,4044.22 2965.29,4032.05 2967.01,4019 2965.29,4005.95 2960.25,3993.78 2952.24,3983.34 2941.79,3975.33 2929.63,3970.29 2916.57,3968.57 2903.52,3970.29 2891.36,3975.33 2880.91,3983.34 2872.9,3993.78 2867.86,4005.95
  pour cut-out: 4968.9,2067.19 4970.62,2080.25 4975.66,2092.41 4983.67,2102.85 4994.12,2110.87 5006.28,2115.91 5019.33,2117.63 5032.38,2115.91 5044.55,2110.87 5054.99,2102.85 5063.01,2092.41 5068.05,2080.25 5069.76,2067.19 5068.05,2054.14 5063.01,2041.98 5054.99,2031.53 5044.55,2023.52 5032.38,2018.48 5019.33,2016.76 5006.28,2018.48 4994.12,2023.52 4983.67,2031.53 4975.66,2041.98 4970.62,2054.14
  pour cut-out: 4968.9,1730.34 4970.62,1743.4 4975.66,1755.56 4983.67,1766 4994.12,1774.02 5006.28,1779.06 5019.33,1780.78 5032.38,1779.06 5044.55,1774.02 5054.99,1766 5063.01,1755.56 5068.05,1743.4 5069.76,1730.34 5068.05,1717.29 5063.01,1705.13 5054.99,1694.68 5044.55,1686.67 5032.38,1681.63 5019.33,1679.91 5006.28,1681.63 4994.12,1686.67 4983.67,1694.68 4975.66,1705.13 4970.62,1717.29
  pour cut-out: 4968.9,1420.34 4970.62,1433.4 4975.66,1445.56 4983.67,1456 4994.12,1464.02 5006.28,1469.06 5019.33,1470.78 5032.38,1469.06 5044.55,1464.02 5054.99,1456 5063.01,1445.56 5068.05,1433.4 5069.76,1420.34 5068.05,1407.29 5063.01,1395.13 5054.99,1384.68 5044.55,1376.67 5032.38,1371.63 5019.33,1369.91 5006.28,1371.63 4994.12,1376.67 4983.67,1384.68 4975.66,1395.13 4970.62,1407.29
  pour cut-out: 4968.9,1083.49 4970.62,1096.55 4975.66,1108.71 4983.67,1119.15 4994.12,1127.17 5006.28,1132.21 5019.33,1133.93 5032.38,1132.21 5044.55,1127.17 5054.99,1119.15 5063.01,1108.71 5068.05,1096.55 5069.76,1083.49 5068.05,1070.44 5063.01,1058.28 5054.99,1047.83 5044.55,1039.82 5032.38,1034.78 5019.33,1033.06 5006.28,1034.78 4994.12,1039.82 4983.67,1047.83 4975.66,1058.28 4970.62,1070.44
  pour cut-out: 4299.24,479 4300.96,492.05 4306,504.22 4314.01,514.66 4324.46,522.67 4336.62,527.71 4349.68,529.43 4362.73,527.71 4374.89,522.67 4385.34,514.66 4393.35,504.22 4398.39,492.05 4400.11,479 4398.39,465.95 4393.35,453.78 4385.34,443.34 4374.89,435.33 4362.73,430.29 4349.68,428.57 4336.62,430.29 4324.46,435.33 4314.01,443.34 4306,453.78 4300.96,465.95
  pour cut-out: 3962.39,479 3964.11,492.05 3969.15,504.22 3977.16,514.66 3987.61,522.67 3999.77,527.71 4012.83,529.43 4025.88,527.71 4038.04,522.67 4048.49,514.66 4056.5,504.22 4061.54,492.05 4063.26,479 4061.54,465.95 4056.5,453.78 4048.49,443.34 4038.04,435.33 4025.88,430.29 4012.83,428.57 3999.77,430.29 3987.61,435.33 3977.16,443.34 3969.15,453.78 3964.11,465.95
  pour cut-out: 3652.39,479 3654.11,492.05 3659.15,504.22 3667.16,514.66 3677.61,522.67 3689.77,527.71 3702.83,529.43 3715.88,527.71 3728.04,522.67 3738.49,514.66 3746.5,504.22 3751.54,492.05 3753.26,479 3751.54,465.95 3746.5,453.78 3738.49,443.34 3728.04,435.33 3715.88,430.29 3702.83,428.57 3689.77,430.29 3677.61,435.33 3667.16,443.34 3659.15,453.78 3654.11,465.95
  pour cut-out: 3315.54,479 3317.26,492.05 3322.3,504.22 3330.31,514.66 3340.76,522.67 3352.92,527.71 3365.98,529.43 3379.03,527.71 3391.19,522.67 3401.64,514.66 3409.65,504.22 3414.69,492.05 3416.41,479 3414.69,465.95 3409.65,453.78 3401.64,443.34 3391.19,435.33 3379.03,430.29 3365.98,428.57 3352.92,430.29 3340.76,435.33 3330.31,443.34 3322.3,453.78 3317.26,465.95
  pour cut-out: 2358.69,479 2360.41,492.05 2365.45,504.22 2373.46,514.66 2383.91,522.67 2396.07,527.71 2409.13,529.43 2422.18,527.71 2434.34,522.67 2444.79,514.66 2452.8,504.22 2457.84,492.05 2459.56,479 2457.84,465.95 2452.8,453.78 2444.79,443.34 2434.34,435.33 2422.18,430.29 2409.13,428.57 2396.07,430.29 2383.91,435.33 2373.46,443.34 2365.45,453.78 2360.41,465.95
  pour cut-out: 2021.84,479 2023.56,492.05 2028.6,504.22 2036.61,514.66 2047.06,522.67 2059.22,527.71 2072.28,529.43 2085.33,527.71 2097.49,522.67 2107.94,514.66 2115.95,504.22 2120.99,492.05 2122.71,479 2120.99,465.95 2115.95,453.78 2107.94,443.34 2097.49,435.33 2085.33,430.29 2072.28,428.57 2059.22,430.29 2047.06,435.33 2036.61,443.34 2028.6,453.78 2023.56,465.95
  pour cut-out: 1711.84,479 1713.56,492.05 1718.6,504.22 1726.61,514.66 1737.06,522.67 1749.22,527.71 1762.28,529.43 1775.33,527.71 1787.49,522.67 1797.94,514.66 1805.95,504.22 1810.99,492.05 1812.71,479 1810.99,465.95 1805.95,453.78 1797.94,443.34 1787.49,435.33 1775.33,430.29 1762.28,428.57 1749.22,430.29 1737.06,435.33 1726.61,443.34 1718.6,453.78 1713.56,465.95
  pour cut-out: 1374.99,479 1376.71,492.05 1381.75,504.22 1389.76,514.66 1400.21,522.67 1412.37,527.71 1425.43,529.43 1438.48,527.71 1450.64,522.67 1461.09,514.66 1469.1,504.22 1474.14,492.05 1475.86,479 1474.14,465.95 1469.1,453.78 1461.09,443.34 1450.64,435.33 1438.48,430.29 1425.43,428.57 1412.37,430.29 1400.21,435.33 1389.76,443.34 1381.75,453.78 1376.71,465.95
  pour cut-out: 1064.99,479 1066.71,492.05 1071.75,504.22 1079.76,514.66 1090.21,522.67 1102.37,527.71 1115.43,529.43 1128.48,527.71 1140.64,522.67 1151.09,514.66 1159.1,504.22 1164.14,492.05 1165.86,479 1164.14,465.95 1159.1,453.78 1151.09,443.34 1140.64,435.33 1128.48,430.29 1115.43,428.57 1102.37,430.29 1090.21,435.33 1079.76,443.34 1071.75,453.78 1066.71,465.95
  pour cut-out: 728.14,479 729.86,492.05 734.9,504.22 742.91,514.66 753.36,522.67 765.52,527.71 778.58,529.43 791.63,527.71 803.79,522.67 814.24,514.66 822.25,504.22 827.29,492.05 829.01,479 827.29,465.95 822.25,453.78 814.24,443.34 803.79,435.33 791.63,430.29 778.58,428.57 765.52,430.29 753.36,435.33 742.91,443.34 734.9,453.78 729.86,465.95
  pour cut-out: 429.57,555.17 431.29,568.23 436.33,580.39 444.34,590.84 454.78,598.85 466.95,603.89 480,605.61 493.05,603.89 505.22,598.85 515.66,590.84 523.67,580.39 528.71,568.23 530.43,555.17 528.71,542.12 523.67,529.96 515.66,519.51 505.22,511.5 493.05,506.46 480,504.74 466.95,506.46 454.78,511.5 444.34,519.51 436.33,529.96 431.29,542.12
  pour cut-out: 429.57,892.02 431.29,905.08 436.33,917.24 444.34,927.69 454.78,935.7 466.95,940.74 480,942.46 493.05,940.74 505.22,935.7 515.66,927.69 523.67,917.24 528.71,905.08 530.43,892.02 528.71,878.97 523.67,866.81 515.66,856.36 505.22,848.35 493.05,843.31 480,841.59 466.95,843.31 454.78,848.35 444.34,856.36 436.33,866.81 431.29,878.97
  pour cut-out: 429.57,1488.87 431.29,1501.93 436.33,1514.09 444.34,1524.54 454.78,1532.55 466.95,1537.59 480,1539.31 493.05,1537.59 505.22,1532.55 515.66,1524.54 523.67,1514.09 528.71,1501.93 530.43,1488.87 528.71,1475.82 523.67,1463.66 515.66,1453.21 505.22,1445.2 493.05,1440.16 480,1438.44 466.95,1440.16 454.78,1445.2 444.34,1453.21 436.33,1463.66 431.29,1475.82
  pour cut-out: 429.57,2345.72 431.29,2358.78 436.33,2370.94 444.34,2381.39 454.78,2389.4 466.95,2394.44 480,2396.16 493.05,2394.44 505.22,2389.4 515.66,2381.39 523.67,2370.94 528.71,2358.78 530.43,2345.72 528.71,2332.67 523.67,2320.51 515.66,2310.06 505.22,2302.05 493.05,2297.01 480,2295.29 466.95,2297.01 454.78,2302.05 444.34,2310.06 436.33,2320.51 431.29,2332.67
  pour cut-out: 429.57,2682.57 431.29,2695.63 436.33,2707.79 444.34,2718.24 454.78,2726.25 466.95,2731.29 480,2733.01 493.05,2731.29 505.22,2726.25 515.66,2718.24 523.67,2707.79 528.71,2695.63 530.43,2682.57 528.71,2669.52 523.67,2657.36 515.66,2646.91 505.22,2638.9 493.05,2633.86 480,2632.14 466.95,2633.86 454.78,2638.9 444.34,2646.91 436.33,2657.36 431.29,2669.52
  pour cut-out: 429.57,1152.02 431.29,1165.08 436.33,1177.24 444.34,1187.69 454.78,1195.7 466.95,1200.74 480,1202.46 493.05,1200.74 505.22,1195.7 515.66,1187.69 523.67,1177.24 528.71,1165.08 530.43,1152.02 528.71,1138.97 523.67,1126.81 515.66,1116.36 505.22,1108.35 493.05,1103.31 480,1101.59 466.95,1103.31 454.78,1108.35 444.34,1116.36 436.33,1126.81 431.29,1138.97
  pour cut-out: 2887.39,1918.45 2924.71,1918.45 2947.42,1895.74 2947.42,1861.47 2938.78,1852.83 2880.3,1911.32
  pour cut-out: 2557.1,2254.04 2683.8,2127.34 2678.23,2121.76 2669.42,2121.76 2669.42,2123.92 2552.22,2241.11 2552.22,2248.94
  pour cut-out: 2517.38,2465.49 2551.32,2499.43 2570.09,2499.43 2577.81,2507.14 2577.81,2513.5 2565.21,2526.1 2563.14,2524.03 2513.35,2524.03 2510.4,2521.08 2510.4,2468.43 2513.45,2465.38
  pour cut-out: 3092.6,2475.86 3059.31,2509.15 3059.31,2524.85 3064.65,2530.19 3082.9,2530.19 3117.66,2495.43 3117.66,2480.53 3112.97,2475.84
  pour cut-out: 2892.17,1260.65 2969.26,1260.65 2969.26,1278.39 2963.74,1283.91 2902.82,1283.91 2892.32,1273.4
  pour cut-out: 2073.73,856.31 2096.38,878.96 2118.9,878.96 2141.83,856.03
  pour cut-out: 1427.79,2378.86 1424.89,2378.86 1391.99,2345.96 1391.99,2284.36 1424.65,2251.69 1428.11,2251.69
  pour cut-out: 1433.8,2803.15 1429.42,2803.15 1395.92,2769.65 1395.92,2720.55 1433.98,2682.49
  pour cut-out: 5333.96,3436.89 5335.68,3449.94 5340.72,3462.1 5348.73,3472.55 5359.18,3480.56 5371.34,3485.6 5384.39,3487.32 5397.45,3485.6 5409.61,3480.56 5420.05,3472.55 5428.07,3462.1 5433.11,3449.94 5434.83,3436.89 5433.11,3423.83 5428.07,3411.67 5420.05,3401.22 5409.61,3393.21 5397.45,3388.17 5384.39,3386.45 5371.34,3388.17 5359.18,3393.21 5348.73,3401.22 5340.72,3411.67 5335.68,3423.83
  pour cut-out: 1790.14,607 1816.51,580.64 2037.14,580.64 2063.51,607
  pour cut-out: 4681.48,1748.68 4664.82,1732.02 4446,1732.02 4427.65,1750.36
  pour cut-out: 2310.49,2160.97 cw(c2310.49,2175.97) 2295.49,2175.97 cw(c2310.49,2175.97) 2310.49,2190.97 cw(c2310.49,2175.97) 2325.49,2175.97 cw(c2310.49,2175.97)
  pour cut-out: 2780.69,2112.34 cw(c2780.69,2127.34) 2765.69,2127.34 cw(c2780.69,2127.34) 2780.69,2142.34 cw(c2780.69,2127.34) 2795.69,2127.34 cw(c2780.69,2127.34)
  pour cut-out: 2785.08,2036.6 cw(c2785.08,2051.6) 2770.08,2051.6 cw(c2785.08,2051.6) 2785.08,2066.6 cw(c2785.08,2051.6) 2800.08,2051.6 cw(c2785.08,2051.6)
  pour cut-out: 3037.13,2179.63 cw(c3037.13,2194.63) 3022.13,2194.63 cw(c3037.13,2194.63) 3037.13,2209.63 cw(c3037.13,2194.63) 3052.13,2194.63 cw(c3037.13,2194.63)
  pour cut-out: 2952.65,2003.85 cw(c2952.65,2018.85) 2937.65,2018.85 cw(c2952.65,2018.85) 2952.65,2033.85 cw(c2952.65,2018.85) 2967.65,2018.85 cw(c2952.65,2018.85)
  pour cut-out: 2138.36,2180.07 cw(c2138.36,2195.07) 2123.36,2195.07 cw(c2138.36,2195.07) 2138.36,2210.07 cw(c2138.36,2195.07) 2153.36,2195.07 cw(c2138.36,2195.07)
  text "4" at 5012.44,637.86 h100
  text ".Layer_Name" at 577,-858.49 h60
